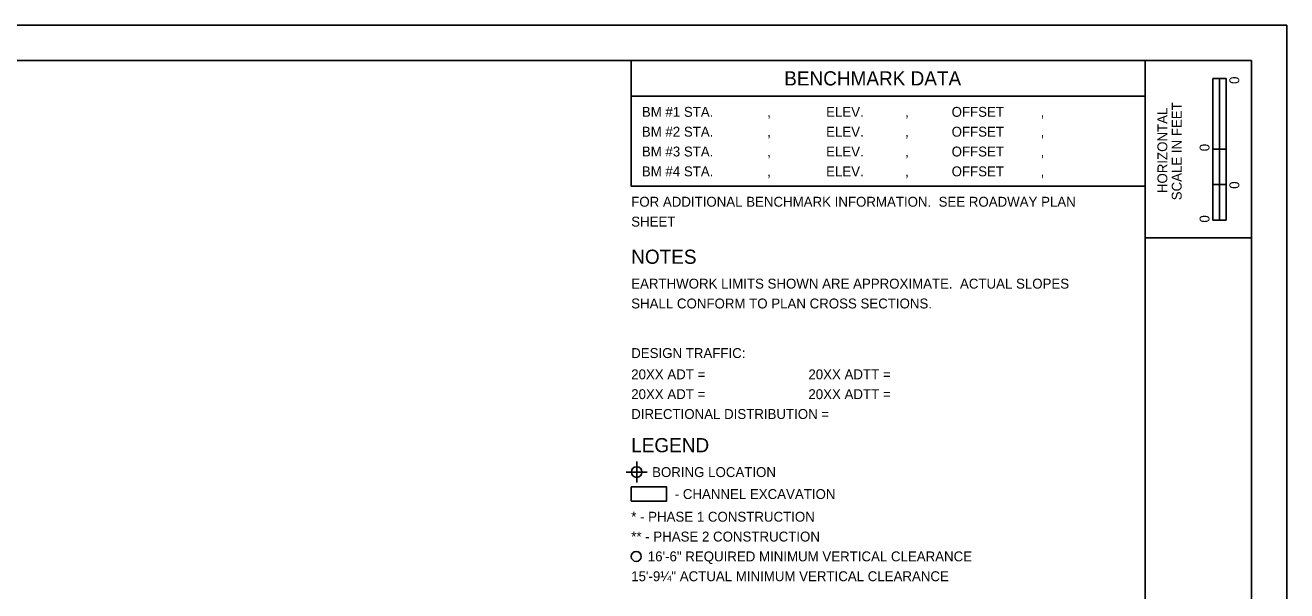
# Model space of a CAD drawing. Extents: x -1.6 to 34, y 0 to 22.
# Drawn here: x 16.2 to 34, y 14.02 to 22 of the extents above; entities that cross this region are included whole.
import ezdxf

# ---------------------------------------------------------------- set-up
doc = ezdxf.new("R2010")
doc.units = 0
for name, color, linetype in [('GT_Project_Soil_Boring', 7, 'Continuous'), ('SH_Border', 7, 'Continuous'), ('SH_Cut_Line', 7, 'Continuous'), ('SH_Data', 7, 'Continuous')]:
    doc.layers.add(name, color=color, linetype=linetype)

msp = doc.modelspace()

# ---------------------------------------------------------------- linework, layer by layer
at = {"layer": 'GT_Project_Soil_Boring'}
for p, q in [((24.827, 15.693), (24.827, 15.843)), ((24.827, 15.693), (24.677, 15.693)), ((24.827, 15.693), (24.752, 15.693)), ((24.827, 15.768), (24.827, 15.693)), ((24.827, 15.693), (24.827, 15.543)), ((24.827, 15.693), (24.977, 15.693)), ((24.827, 15.618), (24.827, 15.693)), ((24.827, 15.693), (24.902, 15.693))]:
    msp.add_line(p, q, dxfattribs=at)
msp.add_circle((24.827, 15.693), 0.075, dxfattribs=at)
for start, end in [(90, 180), (270, 360)]:
    msp.add_arc((24.827, 15.693), 0.075, start, end, dxfattribs=at)
at = {"layer": 'SH_Border'}
for p, q in [((32, 0.5), (32, 21.5)), ((32, 19), (33.5, 19))]:
    msp.add_line(p, q, dxfattribs=at)
msp.add_lwpolyline([(1.5, 21.5), (33.5, 21.5), (33.5, 0.5), (1.5, 0.5)], close=True, dxfattribs=at)
at = {"layer": 'SH_Cut_Line'}
msp.add_lwpolyline([(0, 0), (34, 0), (34, 22), (0, 22)], close=True, dxfattribs=at)
at = {"layer": 'SH_Data'}
for p, q in [((32.957, 20.25), (32.957, 21.25)), ((32.957, 21.25), (33.05, 21.25)), ((32.957, 19.25), (32.957, 21.25)), ((33.144, 21.25), (32.957, 21.25)), ((33.05, 21.25), (33.051, 21.25)), ((33.051, 21.25), (33.051, 20.25)), ((33.144, 21.25), (33.144, 19.25)), ((24.75, 21), (32, 21)), ((33.051, 20.25), (32.957, 20.25)), ((33.143, 20.25), (33.05, 20.25)), ((33.05, 20.25), (33.05, 19.75)), ((33.143, 19.75), (33.143, 20.25)), ((33.05, 19.75), (32.957, 19.75)), ((32.957, 19.75), (32.957, 19.25)), ((33.05, 19.75), (33.143, 19.75)), ((33.05, 19.25), (33.05, 19.75)), ((33.144, 19.25), (32.957, 19.25)), ((32.957, 19.25), (33.05, 19.25))]:
    msp.add_line(p, q, dxfattribs=at)
for points in [[(32, 21.5), (24.75, 21.5), (24.75, 19.727), (32, 19.727)], [(24.75, 15.482), (25.25, 15.482), (25.25, 15.282), (24.75, 15.282)]]:
    msp.add_lwpolyline(points, close=True, dxfattribs=at)
msp.add_circle((24.82, 14.501), 0.07, dxfattribs=at)

# ---------------------------------------------------------------- texts
for s, height, p in [('BENCHMARK DATA', 0.2, (26.909, 21.15)), ('BM #1 STA.', 0.14, (24.9, 20.707)), ('ELEV.', 0.14, (27.5, 20.707)), ('OFFSET', 0.14, (29.271, 20.707)), ('         ,', 0.14, (26.2, 20.707)), ('       ,', 0.14, (28.25, 20.707)), ('      ,', 0.14, (30.215, 20.707)), ('BM #2 STA.', 0.14, (24.9, 20.427)), ('ELEV.', 0.14, (27.5, 20.427)), ('OFFSET', 0.14, (29.271, 20.427)), ('         ,', 0.14, (26.2, 20.427)), ('       ,', 0.14, (28.25, 20.427)), ('      ,', 0.14, (30.215, 20.427)), ('BM #3 STA.', 0.14, (24.9, 20.147)), ('         ,', 0.14, (26.2, 20.147)), ('ELEV.', 0.14, (27.5, 20.147)), ('       ,', 0.14, (28.25, 20.147)), ('OFFSET', 0.14, (29.271, 20.147)), ('      ,', 0.14, (30.215, 20.147)), ('BM #4 STA.', 0.14, (24.9, 19.867)), ('ELEV.', 0.14, (27.5, 19.867)), ('OFFSET', 0.14, (29.271, 19.867)), ('         ,', 0.14, (26.2, 19.867)), ('       ,', 0.14, (28.25, 19.867)), ('      ,', 0.14, (30.215, 19.867)), ('FOR ADDITIONAL BENCHMARK INFORMATION.  SEE ROADWAY PLAN', 0.14, (24.75, 19.438)), ('SHEET      ', 0.14, (24.75, 19.158)), ('NOTES', 0.2, (24.75, 18.632)), ('EARTHWORK LIMITS SHOWN ARE APPROXIMATE.  ACTUAL SLOPES', 0.14, (24.75, 18.282)), ('SHALL CONFORM TO PLAN CROSS SECTIONS.', 0.14, (24.75, 18.002)), ('DESIGN TRAFFIC:', 0.14, (24.75, 17.302)), ('20XX ADT =', 0.14, (24.75, 17.002)), ('20XX ADTT =', 0.14, (27.25, 17.002)), ('20XX ADT =', 0.14, (24.75, 16.722)), ('20XX ADTT =', 0.14, (27.25, 16.722)), ('DIRECTIONAL DISTRIBUTION =', 0.14, (24.75, 16.442)), ('LEGEND', 0.2, (24.75, 15.972)), ('BORING LOCATION', 0.14, (25.045, 15.622)), ('- CHANNEL EXCAVATION', 0.14, (25.364, 15.312)), ('* - PHASE 1 CONSTRUCTION', 0.14, (24.75, 14.992)), ('** - PHASE 2 CONSTRUCTION', 0.14, (24.75, 14.712))]:
    msp.add_text(s, height=height, dxfattribs=at).set_placement(p)
for s, rotation, p in [('0', 90, (33.33, 21.171)), ('HORIZONTAL', 90, (32.315, 19.63)), ('SCALE IN FEET', 90, (32.517, 19.529)), ('0', 90, (32.91, 20.221)), ('0', 90, (33.33, 19.691)), ('0', 90, (32.91, 19.214)), ('16\'-6" REQUIRED MINIMUM VERTICAL CLEARANCE', 0, (24.984, 14.432)), ('15\'-9¼" ACTUAL MINIMUM VERTICAL CLEARANCE', 0, (24.75, 14.152))]:
    msp.add_text(s, height=0.14, rotation=rotation, dxfattribs=at).set_placement(p)

doc.saveas('drawing.dxf')
